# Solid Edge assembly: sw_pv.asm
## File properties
Author: Sham
Template: Sync Iso Assembly.asm
Last saved by: Cadcim
Revision: 4
Application: Solid Edge
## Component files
base.par
Screw.par
moveable jaw.par
handle.par
handle screw.par
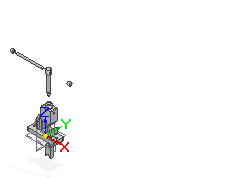
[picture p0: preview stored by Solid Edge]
